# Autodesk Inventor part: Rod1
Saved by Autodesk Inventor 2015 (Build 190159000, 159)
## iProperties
Created: 2015-04
Part Number: Rod1
Material: Generic
Document SubType Name: Modeling
Designer: Gabriel Cabellos
Density: 1 g/cm^3
Appearance: Default
Author: Gabriel Cabellos
Sending System: SolidWorks 2011
Last Author: Pets
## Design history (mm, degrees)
node "Rod1.ipt1"
node "Chamfer2"
node "Base1"
